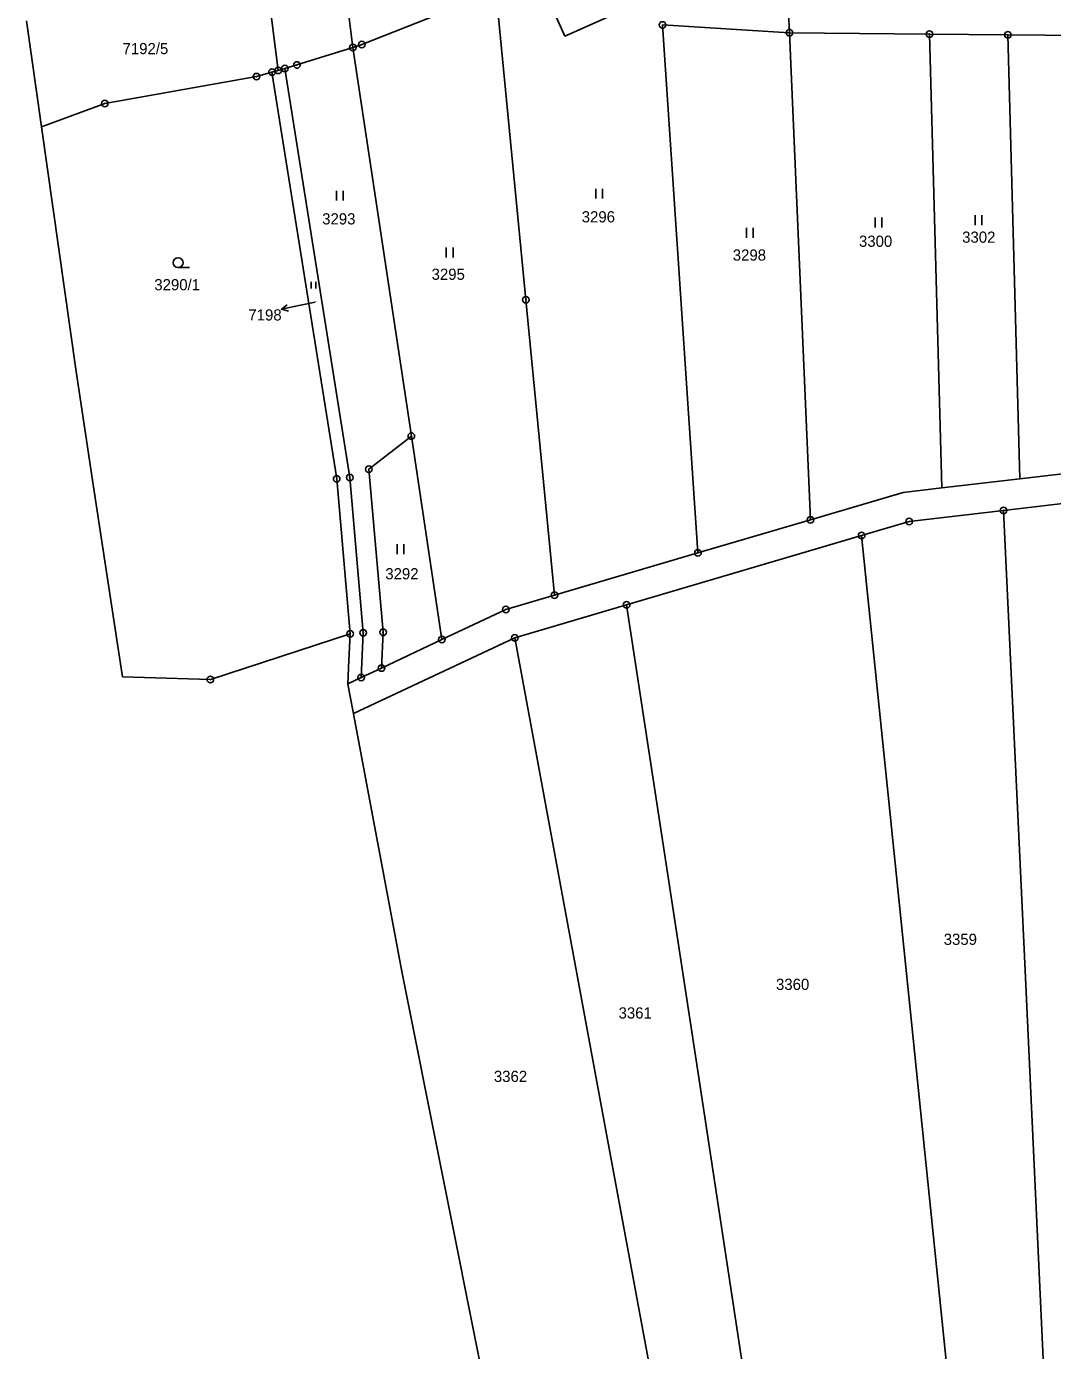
# Model space of a CAD drawing. Extents: x -593183 to -588034, y -1130415 to -1124994.
# Drawn here: x -592752.5 to -592596.5, y -1128548.3 to -1128347 of the extents above; entities that cross this region are included whole.
import ezdxf

# ---------------------------------------------------------------- set-up
doc = ezdxf.new("R2010")
doc.units = 0
for name, color, linetype in [('Vrstva 1', 7, 'Continuous'), ('Vrstva 13', 7, 'Continuous'), ('Vrstva 16', 7, 'Continuous'), ('Vrstva 18', 7, 'Continuous'), ('Vrstva 24', 7, 'Continuous'), ('Vrstva 25', 7, 'Continuous'), ('Vrstva 27', 7, 'Continuous')]:
    doc.layers.add(name, color=color, linetype=linetype)

msp = doc.modelspace()

# ---------------------------------------------------------------- linework, layer by layer
at = {"layer": 'Vrstva 1'}
for p, q in [((-592702.85, -1128350.22), (-592705.36, -1128329.86)), ((-592716.67, -1128334.35), (-592714.18, -1128353.71)), ((-592701.49, -1128349.79), (-592681.1, -1128341.72)), ((-592681.1, -1128341.72), (-592676.55, -1128388.57)), ((-592636.48, -1128347.98), (-592636.61, -1128344.98)), ((-592655.79, -1128346.81), (-592636.48, -1128347.98)), ((-592655.79, -1128346.81), (-592650.39, -1128427.05)), ((-592702.85, -1128350.22), (-592701.49, -1128349.79)), ((-592636.48, -1128347.98), (-592633.29, -1128422.02)), ((-592636.48, -1128347.98), (-592615.19, -1128348.19)), ((-592615.19, -1128348.19), (-592603.27, -1128348.31)), ((-592615.19, -1128348.19), (-592613.33, -1128417.17)), ((-592603.27, -1128348.31), (-592574.41, -1128348.61)), ((-592603.27, -1128348.31), (-592601.45, -1128415.78)), ((-592711.34, -1128352.89), (-592702.85, -1128350.22)), ((-592702.85, -1128350.22), (-592693.96, -1128409.29)), ((-592715.14, -1128353.98), (-592714.18, -1128353.71)), ((-592714.18, -1128353.71), (-592713.2, -1128353.43)), ((-592713.2, -1128353.43), (-592711.34, -1128352.89)), ((-592713.2, -1128353.43), (-592703.32, -1128415.58)), ((-592740.57, -1128358.74), (-592717.49, -1128354.66)), ((-592717.49, -1128354.66), (-592715.14, -1128353.98)), ((-592715.14, -1128353.98), (-592705.31, -1128415.82)), ((-592750.18, -1128362.27), (-592740.57, -1128358.74)), ((-592676.55, -1128388.57), (-592672.19, -1128433.47)), ((-592700.42, -1128414.32), (-592693.96, -1128409.29)), ((-592693.96, -1128409.29), (-592689.31, -1128440.21)), ((-592601.45, -1128415.78), (-592575.47, -1128412.75)), ((-592705.31, -1128415.82), (-592703.26, -1128439.36)), ((-592703.32, -1128415.58), (-592701.27, -1128439.19)), ((-592700.42, -1128414.32), (-592698.26, -1128439.13)), ((-592613.33, -1128417.17), (-592601.45, -1128415.78)), ((-592633.29, -1128422.02), (-592619.19, -1128417.86)), ((-592619.19, -1128417.86), (-592613.33, -1128417.17)), ((-592603.93, -1128420.61), (-592587.85, -1128418.73)), ((-592650.39, -1128427.05), (-592633.29, -1128422.02)), ((-592625.51, -1128424.42), (-592618.29, -1128422.29)), ((-592618.29, -1128422.29), (-592603.93, -1128420.61)), ((-592603.93, -1128420.61), (-592600.66, -1128490.53)), ((-592661.23, -1128434.97), (-592625.51, -1128424.42)), ((-592625.51, -1128424.42), (-592618.13, -1128496.4)), ((-592672.19, -1128433.47), (-592650.39, -1128427.05)), ((-592679.6, -1128435.65), (-592672.19, -1128433.47)), ((-592689.31, -1128440.21), (-592679.6, -1128435.65)), ((-592678.23, -1128439.98), (-592661.23, -1128434.97)), ((-592661.23, -1128434.97), (-592650.22, -1128507.18)), ((-592702.77, -1128451.45), (-592678.23, -1128439.98)), ((-592701.27, -1128439.19), (-592701.57, -1128446.01)), ((-592698.26, -1128439.13), (-592698.5, -1128444.56)), ((-592698.5, -1128444.56), (-592689.31, -1128440.21)), ((-592678.23, -1128439.98), (-592664.89, -1128512.11)), ((-592703.62, -1128446.97), (-592701.57, -1128446.01)), ((-592701.57, -1128446.01), (-592698.5, -1128444.56)), ((-592600.66, -1128490.53), (-592597.44, -1128559.59)), ((-592618.13, -1128496.4), (-592610.98, -1128566.12)), ((-592650.22, -1128507.18), (-592639.62, -1128576.65)), ((-592664.89, -1128512.11), (-592651.76, -1128583.08))]:
    msp.add_line(p, q, dxfattribs=at)
at = {"layer": 'Vrstva 13'}
for p, q in [((-592752.46, -1128346.2), (-592750.18, -1128362.27)), ((-592750.18, -1128362.27), (-592744.9, -1128399.47)), ((-592724.51, -1128446.32), (-592703.26, -1128439.36)), ((-592703.26, -1128439.36), (-592703.45, -1128443.38)), ((-592738.62, -1128440.92), (-592737.87, -1128445.89)), ((-592703.45, -1128443.38), (-592703.62, -1128446.97)), ((-592737.87, -1128445.89), (-592724.51, -1128446.32)), ((-592703.62, -1128446.97), (-592703.3, -1128448.65)), ((-592703.3, -1128448.65), (-592702.77, -1128451.45)), ((-592702.77, -1128451.45), (-592702.76, -1128451.54)), ((-592702.76, -1128451.54), (-592695.33, -1128490.95)), ((-592695.33, -1128490.95), (-592689.46, -1128520.37)), ((-592673.94, -1128598.14), (-592689.46, -1128520.37))]:
    msp.add_line(p, q, dxfattribs=at)
msp.add_lwpolyline([(-592744.9, -1128399.47), (-592742.25, -1128417), (-592738.62, -1128440.92)], dxfattribs=at)
at = {"layer": 'Vrstva 16'}
msp.add_line((-592708.59, -1128388.94), (-592710.79, -1128389.41), dxfattribs=at)
at = {"layer": 'Vrstva 24'}
for centre, radius in [((-592655.79, -1128346.81), 0.5), ((-592636.48, -1128347.98), 0.5), ((-592615.19, -1128348.19), 0.5), ((-592603.27, -1128348.31), 0.5), ((-592702.85, -1128350.22), 0.5), ((-592701.49, -1128349.79), 0.5), ((-592701.49, -1128349.79), 0.0327), ((-592636.48, -1128347.98), 0.0327), ((-592615.19, -1128348.19), 0.0327), ((-592603.27, -1128348.31), 0.0327), ((-592702.85, -1128350.22), 0.0327), ((-592715.14, -1128353.98), 0.5), ((-592714.18, -1128353.71), 0.5), ((-592714.18, -1128353.71), 0.0327), ((-592713.2, -1128353.43), 0.5), ((-592713.2, -1128353.43), 0.0327), ((-592711.34, -1128352.89), 0.5), ((-592711.34, -1128352.89), 0.0327), ((-592717.49, -1128354.66), 0.5), ((-592717.49, -1128354.66), 0.0327), ((-592715.14, -1128353.98), 0.0327), ((-592740.57, -1128358.74), 0.5), ((-592740.57, -1128358.74), 0.0327), ((-592676.55, -1128388.57), 0.5), ((-592676.55, -1128388.57), 0.0327), ((-592693.96, -1128409.29), 0.5), ((-592693.96, -1128409.29), 0.0327), ((-592700.42, -1128414.32), 0.5), ((-592700.42, -1128414.32), 0.0327), ((-592705.31, -1128415.82), 0.5), ((-592705.31, -1128415.82), 0.0327), ((-592703.32, -1128415.58), 0.5), ((-592703.32, -1128415.58), 0.0327), ((-592603.93, -1128420.61), 0.5), ((-592633.29, -1128422.02), 0.5), ((-592633.29, -1128422.02), 0.0327), ((-592618.29, -1128422.29), 0.5), ((-592618.29, -1128422.29), 0.0327), ((-592603.93, -1128420.61), 0.0327), ((-592625.51, -1128424.42), 0.5), ((-592625.51, -1128424.42), 0.0327), ((-592650.39, -1128427.05), 0.5), ((-592650.39, -1128427.05), 0.0327), ((-592672.19, -1128433.47), 0.5), ((-592672.19, -1128433.47), 0.0327), ((-592679.6, -1128435.65), 0.5), ((-592679.6, -1128435.65), 0.0327), ((-592661.23, -1128434.97), 0.5), ((-592661.23, -1128434.97), 0.0327), ((-592703.26, -1128439.36), 0.5), ((-592703.26, -1128439.36), 0.0327), ((-592701.27, -1128439.19), 0.5), ((-592701.27, -1128439.19), 0.0327), ((-592698.26, -1128439.13), 0.5), ((-592698.26, -1128439.13), 0.0327), ((-592689.31, -1128440.21), 0.5), ((-592689.31, -1128440.21), 0.0327), ((-592678.23, -1128439.98), 0.5), ((-592678.23, -1128439.98), 0.0327), ((-592698.5, -1128444.56), 0.5), ((-592724.51, -1128446.32), 0.5), ((-592724.51, -1128446.32), 0.0327), ((-592701.57, -1128446.01), 0.5), ((-592701.57, -1128446.01), 0.0327), ((-592698.5, -1128444.56), 0.0327)]:
    msp.add_circle(centre, radius, dxfattribs=at)
at = {"layer": 'Vrstva 25'}
for p, q in [((-592705.33, -1128372), (-592705.33, -1128373.5)), ((-592704.31, -1128373.5), (-592704.31, -1128372)), ((-592665.9, -1128371.71), (-592665.9, -1128373.21)), ((-592664.88, -1128373.21), (-592664.88, -1128371.71)), ((-592608.24, -1128375.74), (-592608.24, -1128377.24)), ((-592607.22, -1128377.24), (-592607.22, -1128375.74)), ((-592643.03, -1128377.66), (-592643.03, -1128379.16)), ((-592642.01, -1128379.16), (-592642.01, -1128377.66)), ((-592623.44, -1128376.09), (-592623.44, -1128377.59)), ((-592622.42, -1128377.59), (-592622.42, -1128376.09)), ((-592688.65, -1128380.65), (-592688.65, -1128382.15)), ((-592687.62, -1128382.15), (-592687.62, -1128380.65)), ((-592727.66, -1128383.7), (-592729.41, -1128383.7)), ((-592709.19, -1128385.86), (-592709.19, -1128386.86)), ((-592708.5, -1128386.86), (-592708.5, -1128385.86)), ((-592710.79, -1128389.41), (-592713.72, -1128390.03)), ((-592696.1, -1128425.74), (-592696.1, -1128427.24)), ((-592695.08, -1128427.24), (-592695.08, -1128425.74))]:
    msp.add_line(p, q, dxfattribs=at)
msp.add_lwpolyline([(-592712.64, -1128390.31), (-592713.72, -1128390.03), (-592712.85, -1128389.34)], dxfattribs=at)
msp.add_circle((-592729.41, -1128382.95), 0.75, dxfattribs=at)
at = {"layer": 'Vrstva 27'}
for p, q in [((-592670.63, -1128348.53), (-592673.95, -1128341.09)), ((-592656.11, -1128342.05), (-592670.63, -1128348.53))]:
    msp.add_line(p, q, dxfattribs=at)

# ---------------------------------------------------------------- texts
at = {"layer": 'Vrstva 16'}
msp.add_text('7198', height=1.7, dxfattribs=at).set_placement((-592718.73, -1128391.73))
at = {"layer": 'Vrstva 18'}
for s, height, p in [('7192/5', 1.7, (-592737.86, -1128351.25)), ('3293', 1.7, (-592707.51, -1128377.13)), ('3296', 1.7, (-592668.06, -1128376.82)), ('3300', 1.7, (-592625.92, -1128380.53)), ('3302', 1.7, (-592610.23, -1128379.91)), ('3298', 1.7, (-592645.1, -1128382.63)), ('3295', 1.7, (-592690.88, -1128385.55)), ('3290/1', 1.7, (-592733.03, -1128387.14)), ('7198', 0.1, (-592708.59, -1128388.94)), ('3292', 1.7, (-592697.92, -1128431.08)), ('3359', 1.7, (-592613.04, -1128486.65)), ('3360', 1.7, (-592638.53, -1128493.49)), ('3361', 1.7, (-592662.46, -1128497.84)), ('3362', 1.7, (-592681.41, -1128507.48))]:
    msp.add_text(s, height=height, dxfattribs=at).set_placement(p)

doc.saveas('drawing.dxf')
